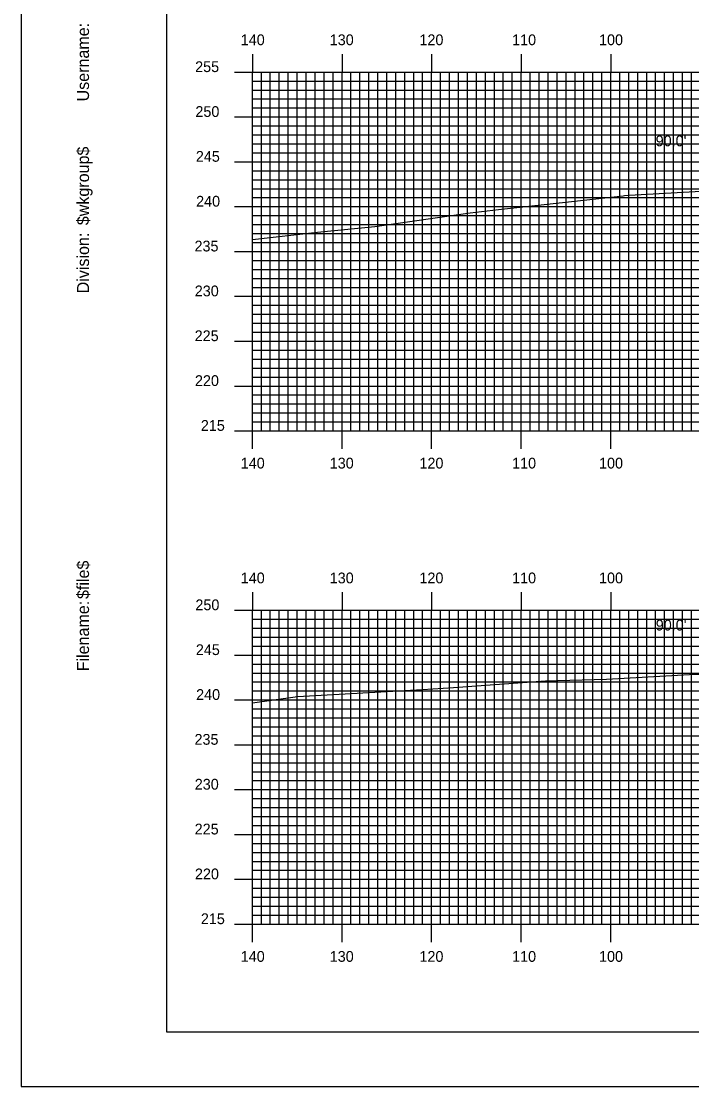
# Model space of a CAD drawing. Extents: x 1817276 to 1817620, y 442591 to 442811.
# Drawn here: x 1817276.3 to 1817351.1, y 442590.5 to 442709.3 of the extents above; entities that cross this region are included whole.
import ezdxf

# ---------------------------------------------------------------- set-up
doc = ezdxf.new("R2010")
doc.units = 0
for name, color, linetype in [('BORDER', 7, 'Continuous'), ('D_Text_Standard', 7, 'Continuous'), ('H_V ANNOTATION', 7, 'Continuous'), ('MAJOR', 7, 'Continuous'), ('MINOR', 7, 'Continuous'), ('PLOT BOUNDARY', 7, 'Continuous'), ('S_Roadway_Centerline', 7, 'Continuous')]:
    doc.layers.add(name, color=color, linetype=linetype)

msp = doc.modelspace()

# ---------------------------------------------------------------- linework, layer by layer
at = {"layer": 'BORDER'}
msp.add_lwpolyline([(1817292.5, 442596.67), (1817612.5, 442596.67), (1817612.5, 442806.67), (1817292.5, 442806.67)], close=True, dxfattribs=at)
at = {"layer": 'MAJOR'}
for p, q in [((1817302.1, 442705.67), (1817302.1, 442703.67)), ((1817312.1, 442705.67), (1817312.1, 442703.67)), ((1817322.1, 442705.67), (1817322.1, 442703.67)), ((1817332.1, 442705.67), (1817332.1, 442703.67)), ((1817342.1, 442705.67), (1817342.1, 442703.67)), ((1817300.1, 442703.67), (1817302.1, 442703.67)), ((1817302.1, 442703.67), (1817582.1, 442703.67)), ((1817302.1, 442663.67), (1817302.1, 442703.67)), ((1817302.1, 442663.67), (1817302.1, 442703.67)), ((1817302.1, 442703.67), (1817582.1, 442703.67)), ((1817312.1, 442663.67), (1817312.1, 442703.67)), ((1817322.1, 442663.67), (1817322.1, 442703.67)), ((1817332.1, 442663.67), (1817332.1, 442703.67)), ((1817342.1, 442663.67), (1817342.1, 442703.67)), ((1817300.1, 442698.67), (1817302.1, 442698.67)), ((1817302.1, 442698.67), (1817582.1, 442698.67)), ((1817300.1, 442693.67), (1817302.1, 442693.67)), ((1817302.1, 442693.67), (1817582.1, 442693.67)), ((1817300.1, 442688.67), (1817302.1, 442688.67)), ((1817302.1, 442688.67), (1817582.1, 442688.67)), ((1817300.1, 442683.67), (1817302.1, 442683.67)), ((1817302.1, 442683.67), (1817582.1, 442683.67)), ((1817300.1, 442678.67), (1817302.1, 442678.67)), ((1817302.1, 442678.67), (1817582.1, 442678.67)), ((1817300.1, 442673.67), (1817302.1, 442673.67)), ((1817302.1, 442673.67), (1817582.1, 442673.67)), ((1817300.1, 442668.67), (1817302.1, 442668.67)), ((1817302.1, 442668.67), (1817582.1, 442668.67)), ((1817300.1, 442663.67), (1817302.1, 442663.67)), ((1817302.1, 442663.67), (1817582.1, 442663.67)), ((1817302.1, 442663.67), (1817582.1, 442663.67)), ((1817302.1, 442661.66), (1817302.1, 442663.67)), ((1817312.1, 442661.66), (1817312.1, 442663.67)), ((1817322.1, 442661.66), (1817322.1, 442663.67)), ((1817332.1, 442661.66), (1817332.1, 442663.67)), ((1817342.1, 442661.66), (1817342.1, 442663.67)), ((1817302.1, 442645.67), (1817302.1, 442643.67)), ((1817312.1, 442645.67), (1817312.1, 442643.67)), ((1817322.1, 442645.67), (1817322.1, 442643.67)), ((1817332.1, 442645.67), (1817332.1, 442643.67)), ((1817342.1, 442645.67), (1817342.1, 442643.67)), ((1817300.1, 442643.67), (1817302.1, 442643.67)), ((1817302.1, 442643.67), (1817582.1, 442643.67)), ((1817302.1, 442608.67), (1817302.1, 442643.67)), ((1817302.1, 442608.67), (1817302.1, 442643.67)), ((1817302.1, 442643.67), (1817582.1, 442643.67)), ((1817312.1, 442608.67), (1817312.1, 442643.67)), ((1817322.1, 442608.67), (1817322.1, 442643.67)), ((1817332.1, 442608.67), (1817332.1, 442643.67)), ((1817342.1, 442608.67), (1817342.1, 442643.67)), ((1817300.1, 442638.67), (1817302.1, 442638.67)), ((1817302.1, 442638.67), (1817582.1, 442638.67)), ((1817300.1, 442633.67), (1817302.1, 442633.67)), ((1817302.1, 442633.67), (1817582.1, 442633.67)), ((1817300.1, 442628.67), (1817302.1, 442628.67)), ((1817302.1, 442628.67), (1817582.1, 442628.67)), ((1817300.1, 442623.67), (1817302.1, 442623.67)), ((1817302.1, 442623.67), (1817582.1, 442623.67)), ((1817300.1, 442618.67), (1817302.1, 442618.67)), ((1817302.1, 442618.67), (1817582.1, 442618.67)), ((1817300.1, 442613.67), (1817302.1, 442613.67)), ((1817302.1, 442613.67), (1817582.1, 442613.67)), ((1817300.1, 442608.67), (1817302.1, 442608.67)), ((1817302.1, 442608.67), (1817582.1, 442608.67)), ((1817302.1, 442608.67), (1817582.1, 442608.67)), ((1817302.1, 442606.66), (1817302.1, 442608.67)), ((1817312.1, 442606.66), (1817312.1, 442608.67)), ((1817322.1, 442606.66), (1817322.1, 442608.67)), ((1817332.1, 442606.66), (1817332.1, 442608.67)), ((1817342.1, 442606.66), (1817342.1, 442608.67))]:
    msp.add_line(p, q, dxfattribs=at)
at = {"layer": 'MINOR'}
for p, q in [((1817302.1, 442702.67), (1817582.1, 442702.67)), ((1817302.1, 442702.67), (1817304.1, 442702.67)), ((1817303.1, 442663.67), (1817303.1, 442703.67)), ((1817304.1, 442663.67), (1817304.1, 442703.67)), ((1817305.1, 442663.67), (1817305.1, 442703.67)), ((1817306.1, 442663.67), (1817306.1, 442703.67)), ((1817307.1, 442663.67), (1817307.1, 442703.67)), ((1817308.1, 442663.67), (1817308.1, 442703.67)), ((1817309.1, 442663.67), (1817309.1, 442703.67)), ((1817310.1, 442663.67), (1817310.1, 442703.67)), ((1817311.1, 442663.67), (1817311.1, 442703.67)), ((1817313.1, 442663.67), (1817313.1, 442703.67)), ((1817314.1, 442663.67), (1817314.1, 442703.67)), ((1817315.1, 442663.67), (1817315.1, 442703.67)), ((1817316.1, 442663.67), (1817316.1, 442703.67)), ((1817317.1, 442663.67), (1817317.1, 442703.67)), ((1817318.1, 442663.67), (1817318.1, 442703.67)), ((1817319.1, 442663.67), (1817319.1, 442703.67)), ((1817320.1, 442663.67), (1817320.1, 442703.67)), ((1817321.1, 442663.67), (1817321.1, 442703.67)), ((1817323.1, 442663.67), (1817323.1, 442703.67)), ((1817324.1, 442663.67), (1817324.1, 442703.67)), ((1817325.1, 442663.67), (1817325.1, 442703.67)), ((1817326.1, 442663.67), (1817326.1, 442703.67)), ((1817327.1, 442663.67), (1817327.1, 442703.67)), ((1817328.1, 442663.67), (1817328.1, 442703.67)), ((1817329.1, 442663.67), (1817329.1, 442703.67)), ((1817330.1, 442663.67), (1817330.1, 442703.67)), ((1817331.1, 442663.67), (1817331.1, 442703.67)), ((1817333.1, 442663.67), (1817333.1, 442703.67)), ((1817334.1, 442663.67), (1817334.1, 442703.67)), ((1817335.1, 442663.67), (1817335.1, 442703.67)), ((1817336.1, 442663.67), (1817336.1, 442703.67)), ((1817337.1, 442663.67), (1817337.1, 442703.67)), ((1817338.1, 442663.67), (1817338.1, 442703.67)), ((1817339.1, 442663.67), (1817339.1, 442703.67)), ((1817340.1, 442663.67), (1817340.1, 442703.67)), ((1817341.1, 442663.67), (1817341.1, 442703.67)), ((1817343.1, 442663.67), (1817343.1, 442703.67)), ((1817344.1, 442663.67), (1817344.1, 442703.67)), ((1817345.1, 442663.67), (1817345.1, 442703.67)), ((1817346.1, 442663.67), (1817346.1, 442703.67)), ((1817347.1, 442663.67), (1817347.1, 442703.67)), ((1817348.1, 442663.67), (1817348.1, 442703.67)), ((1817349.1, 442663.67), (1817349.1, 442703.67)), ((1817350.1, 442663.67), (1817350.1, 442703.67)), ((1817351.1, 442663.67), (1817351.1, 442703.67)), ((1817302.1, 442701.67), (1817582.1, 442701.67)), ((1817302.1, 442701.67), (1817304.1, 442701.67)), ((1817302.1, 442700.67), (1817582.1, 442700.67)), ((1817302.1, 442700.67), (1817304.1, 442700.67)), ((1817302.1, 442699.67), (1817582.1, 442699.67)), ((1817302.1, 442699.67), (1817304.1, 442699.67)), ((1817302.1, 442697.67), (1817582.1, 442697.67)), ((1817302.1, 442697.67), (1817304.1, 442697.67)), ((1817302.1, 442696.67), (1817582.1, 442696.67)), ((1817302.1, 442696.67), (1817304.1, 442696.67)), ((1817302.1, 442695.67), (1817582.1, 442695.67)), ((1817302.1, 442695.67), (1817304.1, 442695.67)), ((1817302.1, 442694.67), (1817582.1, 442694.67)), ((1817302.1, 442694.67), (1817304.1, 442694.67)), ((1817302.1, 442692.67), (1817582.1, 442692.67)), ((1817302.1, 442692.67), (1817304.1, 442692.67)), ((1817302.1, 442691.67), (1817582.1, 442691.67)), ((1817302.1, 442691.67), (1817304.1, 442691.67)), ((1817302.1, 442690.67), (1817582.1, 442690.67)), ((1817302.1, 442690.67), (1817304.1, 442690.67)), ((1817302.1, 442689.67), (1817582.1, 442689.67)), ((1817302.1, 442689.67), (1817304.1, 442689.67)), ((1817302.1, 442687.67), (1817582.1, 442687.67)), ((1817302.1, 442687.67), (1817304.1, 442687.67)), ((1817302.1, 442686.67), (1817582.1, 442686.67)), ((1817302.1, 442686.67), (1817304.1, 442686.67)), ((1817302.1, 442685.67), (1817582.1, 442685.67)), ((1817302.1, 442685.67), (1817304.1, 442685.67)), ((1817302.1, 442684.67), (1817582.1, 442684.67)), ((1817302.1, 442684.67), (1817304.1, 442684.67)), ((1817302.1, 442682.67), (1817582.1, 442682.67)), ((1817302.1, 442682.67), (1817304.1, 442682.67)), ((1817302.1, 442681.67), (1817582.1, 442681.67)), ((1817302.1, 442681.67), (1817304.1, 442681.67)), ((1817302.1, 442680.67), (1817582.1, 442680.67)), ((1817302.1, 442680.67), (1817304.1, 442680.67)), ((1817302.1, 442679.67), (1817582.1, 442679.67)), ((1817302.1, 442679.67), (1817304.1, 442679.67)), ((1817302.1, 442677.67), (1817582.1, 442677.67)), ((1817302.1, 442677.67), (1817304.1, 442677.67)), ((1817302.1, 442676.67), (1817582.1, 442676.67)), ((1817302.1, 442676.67), (1817304.1, 442676.67)), ((1817302.1, 442675.67), (1817582.1, 442675.67)), ((1817302.1, 442675.67), (1817304.1, 442675.67)), ((1817302.1, 442674.67), (1817582.1, 442674.67)), ((1817302.1, 442674.67), (1817304.1, 442674.67)), ((1817302.1, 442672.67), (1817582.1, 442672.67)), ((1817302.1, 442672.67), (1817304.1, 442672.67)), ((1817302.1, 442671.67), (1817582.1, 442671.67)), ((1817302.1, 442671.67), (1817304.1, 442671.67)), ((1817302.1, 442670.67), (1817582.1, 442670.67)), ((1817302.1, 442670.67), (1817304.1, 442670.67)), ((1817302.1, 442669.67), (1817582.1, 442669.67)), ((1817302.1, 442669.67), (1817304.1, 442669.67)), ((1817302.1, 442667.67), (1817582.1, 442667.67)), ((1817302.1, 442667.67), (1817304.1, 442667.67)), ((1817302.1, 442666.67), (1817582.1, 442666.67)), ((1817302.1, 442666.67), (1817304.1, 442666.67)), ((1817302.1, 442665.67), (1817582.1, 442665.67)), ((1817302.1, 442665.67), (1817304.1, 442665.67)), ((1817302.1, 442664.67), (1817582.1, 442664.67)), ((1817302.1, 442664.67), (1817304.1, 442664.67)), ((1817303.1, 442608.67), (1817303.1, 442643.67)), ((1817304.1, 442608.67), (1817304.1, 442643.67)), ((1817305.1, 442608.67), (1817305.1, 442643.67)), ((1817306.1, 442608.67), (1817306.1, 442643.67)), ((1817307.1, 442608.67), (1817307.1, 442643.67)), ((1817308.1, 442608.67), (1817308.1, 442643.67)), ((1817309.1, 442608.67), (1817309.1, 442643.67)), ((1817310.1, 442608.67), (1817310.1, 442643.67)), ((1817311.1, 442608.67), (1817311.1, 442643.67)), ((1817313.1, 442608.67), (1817313.1, 442643.67)), ((1817314.1, 442608.67), (1817314.1, 442643.67)), ((1817315.1, 442608.67), (1817315.1, 442643.67)), ((1817316.1, 442608.67), (1817316.1, 442643.67)), ((1817317.1, 442608.67), (1817317.1, 442643.67)), ((1817318.1, 442608.67), (1817318.1, 442643.67)), ((1817319.1, 442608.67), (1817319.1, 442643.67)), ((1817320.1, 442608.67), (1817320.1, 442643.67)), ((1817321.1, 442608.67), (1817321.1, 442643.67)), ((1817323.1, 442608.67), (1817323.1, 442643.67)), ((1817324.1, 442608.67), (1817324.1, 442643.67)), ((1817325.1, 442608.67), (1817325.1, 442643.67)), ((1817326.1, 442608.67), (1817326.1, 442643.67)), ((1817327.1, 442608.67), (1817327.1, 442643.67)), ((1817328.1, 442608.67), (1817328.1, 442643.67)), ((1817329.1, 442608.67), (1817329.1, 442643.67)), ((1817330.1, 442608.67), (1817330.1, 442643.67)), ((1817331.1, 442608.67), (1817331.1, 442643.67)), ((1817333.1, 442608.67), (1817333.1, 442643.67)), ((1817334.1, 442608.67), (1817334.1, 442643.67)), ((1817335.1, 442608.67), (1817335.1, 442643.67)), ((1817336.1, 442608.67), (1817336.1, 442643.67)), ((1817337.1, 442608.67), (1817337.1, 442643.67)), ((1817338.1, 442608.67), (1817338.1, 442643.67)), ((1817339.1, 442608.67), (1817339.1, 442643.67)), ((1817340.1, 442608.67), (1817340.1, 442643.67)), ((1817341.1, 442608.67), (1817341.1, 442643.67)), ((1817343.1, 442608.67), (1817343.1, 442643.67)), ((1817344.1, 442608.67), (1817344.1, 442643.67)), ((1817345.1, 442608.67), (1817345.1, 442643.67)), ((1817346.1, 442608.67), (1817346.1, 442643.67)), ((1817347.1, 442608.67), (1817347.1, 442643.67)), ((1817348.1, 442608.67), (1817348.1, 442643.67)), ((1817349.1, 442608.67), (1817349.1, 442643.67)), ((1817350.1, 442608.67), (1817350.1, 442643.67)), ((1817351.1, 442608.67), (1817351.1, 442643.67)), ((1817302.1, 442642.67), (1817582.1, 442642.67)), ((1817302.1, 442642.67), (1817304.1, 442642.67)), ((1817302.1, 442641.67), (1817582.1, 442641.67)), ((1817302.1, 442641.67), (1817304.1, 442641.67)), ((1817302.1, 442640.67), (1817582.1, 442640.67)), ((1817302.1, 442640.67), (1817304.1, 442640.67)), ((1817302.1, 442639.67), (1817582.1, 442639.67)), ((1817302.1, 442639.67), (1817304.1, 442639.67)), ((1817302.1, 442637.67), (1817582.1, 442637.67)), ((1817302.1, 442637.67), (1817304.1, 442637.67)), ((1817302.1, 442636.67), (1817582.1, 442636.67)), ((1817302.1, 442636.67), (1817304.1, 442636.67)), ((1817302.1, 442635.67), (1817582.1, 442635.67)), ((1817302.1, 442635.67), (1817304.1, 442635.67)), ((1817302.1, 442634.67), (1817582.1, 442634.67)), ((1817302.1, 442634.67), (1817304.1, 442634.67)), ((1817302.1, 442632.67), (1817582.1, 442632.67)), ((1817302.1, 442632.67), (1817304.1, 442632.67)), ((1817302.1, 442631.67), (1817582.1, 442631.67)), ((1817302.1, 442631.67), (1817304.1, 442631.67)), ((1817302.1, 442630.67), (1817582.1, 442630.67)), ((1817302.1, 442630.67), (1817304.1, 442630.67)), ((1817302.1, 442629.67), (1817582.1, 442629.67)), ((1817302.1, 442629.67), (1817304.1, 442629.67)), ((1817302.1, 442627.67), (1817582.1, 442627.67)), ((1817302.1, 442627.67), (1817304.1, 442627.67)), ((1817302.1, 442626.67), (1817582.1, 442626.67)), ((1817302.1, 442626.67), (1817304.1, 442626.67)), ((1817302.1, 442625.67), (1817582.1, 442625.67)), ((1817302.1, 442625.67), (1817304.1, 442625.67)), ((1817302.1, 442624.67), (1817582.1, 442624.67)), ((1817302.1, 442624.67), (1817304.1, 442624.67)), ((1817302.1, 442622.67), (1817582.1, 442622.67)), ((1817302.1, 442622.67), (1817304.1, 442622.67)), ((1817302.1, 442621.67), (1817582.1, 442621.67)), ((1817302.1, 442621.67), (1817304.1, 442621.67)), ((1817302.1, 442620.67), (1817582.1, 442620.67)), ((1817302.1, 442620.67), (1817304.1, 442620.67)), ((1817302.1, 442619.67), (1817582.1, 442619.67)), ((1817302.1, 442619.67), (1817304.1, 442619.67)), ((1817302.1, 442617.67), (1817582.1, 442617.67)), ((1817302.1, 442617.67), (1817304.1, 442617.67)), ((1817302.1, 442616.67), (1817582.1, 442616.67)), ((1817302.1, 442616.67), (1817304.1, 442616.67)), ((1817302.1, 442615.67), (1817582.1, 442615.67)), ((1817302.1, 442615.67), (1817304.1, 442615.67)), ((1817302.1, 442614.67), (1817582.1, 442614.67)), ((1817302.1, 442614.67), (1817304.1, 442614.67)), ((1817302.1, 442612.67), (1817582.1, 442612.67)), ((1817302.1, 442612.67), (1817304.1, 442612.67)), ((1817302.1, 442611.67), (1817582.1, 442611.67)), ((1817302.1, 442611.67), (1817304.1, 442611.67)), ((1817302.1, 442610.67), (1817582.1, 442610.67)), ((1817302.1, 442610.67), (1817304.1, 442610.67)), ((1817302.1, 442609.67), (1817582.1, 442609.67)), ((1817302.1, 442609.67), (1817304.1, 442609.67))]:
    msp.add_line(p, q, dxfattribs=at)
at = {"layer": 'PLOT BOUNDARY'}
msp.add_lwpolyline([(1817276.31, 442590.55), (1817616.31, 442590.55), (1817616.31, 442810.55), (1817276.31, 442810.55)], close=True, dxfattribs=at)
at = {"layer": 'S_Roadway_Centerline'}
for points in [[(1817302.1, 442685), (1817309.37, 442685.81), (1817315.76, 442686.47), (1817326.41, 442687.96), (1817329.55, 442688.35), (1817343.48, 442689.89), (1817343.63, 442689.9), (1817344.15, 442689.94), (1817353.51, 442690.47)], [(1817302.1, 442633.36), (1817306.89, 442634.01), (1817307.14, 442634.04), (1817321.09, 442634.84), (1817324.55, 442635.05), (1817334.82, 442635.8), (1817341.61, 442635.99), (1817350.88, 442636.52), (1817357.89, 442636.64)]]:
    msp.add_lwpolyline(points, dxfattribs=at)

# ---------------------------------------------------------------- texts
at = {"layer": 'BORDER'}
for s, p in [('Username:', (1817283.87, 442700.4)), ('$wkgroup$', (1817283.87, 442686.6)), ('Division:', (1817283.87, 442679)), ('$file$', (1817283.87, 442644.92)), ('Filename:', (1817283.87, 442636.86))]:
    msp.add_text(s, height=1.339, rotation=90, dxfattribs=at).set_placement(p)
at = {"layer": 'D_Text_Standard'}
for p in [(1817347.1, 442695.4), (1817347.11, 442641.41)]:
    msp.add_text("90.0'", height=1.2, dxfattribs=at).set_placement(p)
at = {"layer": 'H_V ANNOTATION'}
for s, p in [('140', (1817300.8, 442706.67)), ('130', (1817310.73, 442706.67)), ('120', (1817320.74, 442706.67)), ('110', (1817331.08, 442706.67)), ('100', (1817340.78, 442706.67)), ('255', (1817295.71, 442703.67)), ('250', (1817295.74, 442698.67)), ('245', (1817295.79, 442693.67)), ('240', (1817295.82, 442688.67)), ('235', (1817295.64, 442683.67)), ('230', (1817295.67, 442678.67)), ('225', (1817295.66, 442673.67)), ('220', (1817295.69, 442668.67)), ('215', (1817296.35, 442663.67)), ('140', (1817300.8, 442659.47)), ('130', (1817310.73, 442659.47)), ('120', (1817320.74, 442659.47)), ('110', (1817331.08, 442659.47)), ('100', (1817340.78, 442659.47)), ('140', (1817300.8, 442646.67)), ('130', (1817310.73, 442646.67)), ('120', (1817320.74, 442646.67)), ('110', (1817331.08, 442646.67)), ('100', (1817340.78, 442646.67)), ('250', (1817295.74, 442643.67)), ('245', (1817295.79, 442638.67)), ('240', (1817295.82, 442633.67)), ('235', (1817295.64, 442628.67)), ('230', (1817295.67, 442623.67)), ('225', (1817295.66, 442618.67)), ('220', (1817295.69, 442613.67)), ('215', (1817296.35, 442608.67)), ('140', (1817300.8, 442604.47)), ('130', (1817310.73, 442604.47)), ('120', (1817320.74, 442604.47)), ('110', (1817331.08, 442604.47)), ('100', (1817340.78, 442604.47))]:
    msp.add_text(s, height=1.2, dxfattribs=at).set_placement(p)
at = {"layer": 'MAJOR'}
for p in [(1817302.09, 442663.67), (1817302.09, 442608.67)]:
    msp.add_text('-', height=0.012, dxfattribs=at).set_placement(p)

doc.saveas('drawing.dxf')
